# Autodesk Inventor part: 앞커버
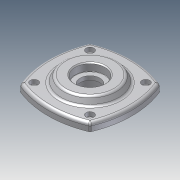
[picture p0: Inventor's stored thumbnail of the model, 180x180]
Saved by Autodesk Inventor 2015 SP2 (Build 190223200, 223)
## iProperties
Created: 2013-02
Part Number: 앞커버
Document SubType Name: Modeling
Designer: 한국산업디자인학원[gmhk.co.kr]
Density: 1 g/cm^3
Material: 일반
Appearance: 기본값
Author: 한국산업디자인학원[gmhk.co.kr]
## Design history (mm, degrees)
sketch "스케치1"
  geometry: C1 r 30 at (0, 0) reference; A1 r 91.05 centre (0, -48.55) between (34.185, 35.839) and (-34.185, 35.839) reference; A2 r 91.05 centre (48.55, 0) between (-35.839, 34.185) and (-35.839, -34.185) reference; A3 r 3 centre (-33.058, 33.058) between (-34.185, 35.839) and (-35.839, 34.185) reference; A4 r 3 centre (33.058, 33.058) between (35.839, 34.185) and (34.185, 35.839) reference; A5 r 91.05 centre (-48.55, 0) between (35.839, -34.185) and (35.839, 34.185) reference; A6 r 3 centre (33.058, -33.058) between (34.185, -35.839) and (35.839, -34.185) reference; A7 r 91.05 centre (0, 48.55) between (-34.185, -35.839) and (34.185, -35.839) reference; A8 r 3 centre (-33.058, -33.058) between (-35.839, -34.185) and (-34.185, -35.839) reference; 1 further point
  node "참조1"
  node "참조2"
  node "참조3"
  node "참조4"
  node "참조5"
  node "참조6"
  node "참조7"
  node "참조8"
  node "참조9"
extrude "돌출1" new body sketch "스케치1" distance "d0" = 8; taper "d1" = 0 deg
sketch "스케치2"
  geometry: C1 r 30 at (0, 0); 1 further point
  constraints: 1 centre point, 1 coincident
  dimensions: "d2" = 60 diameter of C1
extrude "돌출2" join sketch "스케치2" distance "d3" = 7; taper "d4" = -30 deg
hole "구멍1" diameter "d7" = 20; stored, may be unused: countersink angle "d11" = 90 deg, drill point angle "d13" = 118 deg; dims "d5" = 10, "d6" = 10, "d8" = 6, "d9" = 30, "d10" = 8, "d12" = 20
sketch "스케치3"
  geometry: C1 r 1.621 at (28.284, 28.284) reference; C2 r 1.621 at (-28.284, 28.284) reference; C3 r 1.621 at (-28.284, -28.284) reference; C4 r 1.621 at (28.284, -28.284) reference; 1 further point
hole "구멍2" sketch "스케치3" at (28.284, 28.284), (28.284, -28.284), (-28.284, -28.284), (-28.284, 28.284) diameter "d14" = 4.5; stored, may be unused: countersink angle "d18" = 90 deg, drill point angle "d20" = 118 deg; dims "d15" = 6, "d16" = 8, "d17" = 4.4, "d19" = 20
extrude "돌출3" join sketch "스케치1" distance "d21" = 12; taper "d22" = 0 deg
hole "구멍3" diameter "d25" = 30; stored, may be unused: countersink angle "d29" = 90 deg, drill point angle "d31" = 0 deg; dims "d23" = 10, "d24" = 10, "d26" = 6, "d27" = 40, "d28" = 12, "d30" = 15
fillet "모깎기1" dims "d32" = 3, "d33" = 0.3
chamfer "모따기1" distance "d34" = 1; stored, may be unused: second distance "d35" = 2, angle "d36" = 45 deg
node "솔리드1"
node "참조10"
node "참조11"
node "참조12"
node "참조13"
